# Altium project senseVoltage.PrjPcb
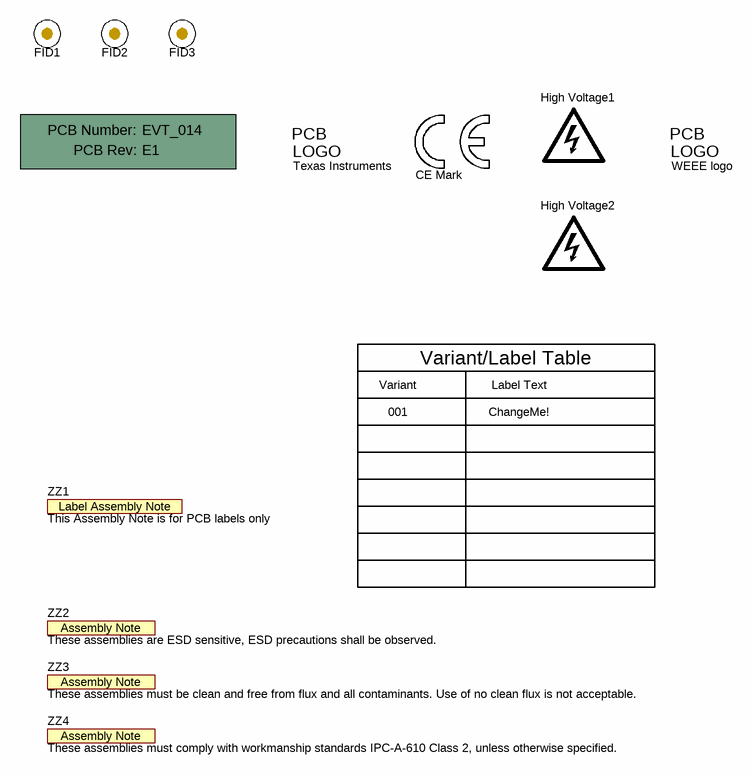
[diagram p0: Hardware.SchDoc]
CopyrightYear: 2018; PCB_Layout: Ramesh Ramamoorthy; PCB_Rev: E1; PRJ_Customer: EV Traction; PRJ_Engineer: Enter name of project lead; PRJ_Number: EVT_014; PRJ_Title: Isolated Sensing of Inverter and DC Bus Voltages; SCH_Rev: E1; TechSupport: http://www.ti.com/support; TID: N/A
2 sheets, 85 parts. Net scope: flat (ports and power ports of the same name join across sheets).
Board file: senseVoltage_r2.PcbDoc
Sheets:
  Hardware.SchDoc
  voltageSense_EVT.SchDoc

## Sheet Hardware.SchDoc
size 431 x 279 mm; Date: Not shown in title block; ApprovedBy: Not shown in title block; CheckedBy: Not shown in title block; Author: Not shown in title block; CompanyName: Not shown in title block; Engineer: Not shown in title block; Organization: Not shown in title block; Address1: Not shown in title block; Address2: Not shown in title block; Address3: Not shown in title block; Address4: Not shown in title block; DocumentNumber: 3; Revision: Use project parameter SCH_Rev; SheetNumber: 3; SheetTotal: 3; PageSetup: Record=PageOptions¦CenterHorizontal=True¦CenterVertical=True¦PrintScale=1.00¦XCorrection=1.00¦YCorrection=1.00¦PrintKind=0¦BorderSize=5000000¦LeftOffset=0¦BottomOffset=0¦Orientation=2¦PaperLength=1000¦PaperWidth=1000¦Scale=100¦PaperSource=15¦PrintQuality=600¦MediaType=1¦DitherType=10¦PaperKind=Letter¦PrintScaleMode=1

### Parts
!PCB1  Printed Circuit Board  (value not drawn)  (mechanical)
FID1  Fiducial  [Fiducial10-20]  (value not drawn)
FID2  Fiducial  [Fiducial10-20]  (value not drawn)
FID3  Fiducial  [Fiducial10-20]  (value not drawn)
High_Voltage1  DANGER HIGH VOLTAGE  [IEC_HighVoltage_Small]  (value not drawn)  (no BOM)
High_Voltage2  DANGER HIGH VOLTAGE  [IEC_HighVoltage_Small]  (value not drawn)  (no BOM)
Logo1  Texas Instruments  [TI_Stacked_Overlay_Small]  (no BOM)
Logo2  CE Mark  [CE_Mark_5mm]  (no BOM)
Logo3  WEEE logo  [WEEE_Minimum]  (no BOM)
ZZ1  This Assembly Note is for PCB labels only  [AssemblyNoteLabel]  (no BOM)
ZZ2  These assemblies are ESD sensitive, ESD precautions shall be observed.  [AssemblyNote]  (no BOM)
ZZ3  These assemblies must be clean and free from flux and all contaminants. Use of no clean flux is not acceptable.  [AssemblyNote]  (no BOM)
ZZ4  These assemblies must comply with workmanship standards IPC-A-610 Class 2, unless otherwise specified.  [AssemblyNote]  (no BOM)

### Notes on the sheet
- Variant
- Variant/Label Table
- Label Text
- 001
- ChangeMe!

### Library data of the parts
!PCB1 = CMP-0003618-2: Manufacturer: Any; PartNumber: EVT_014
FID1-FID3 = CMP-0077181-1: Fiducial mark.  There is nothing to buy or mount.
High_Voltage1 High_Voltage2 = CMP-0074835-1: IEC 61010-1 High Voltage Warning; SymbolCreator: a0412235
Logo1 = CMP-0074838-1: Texas Instrument Corporate Signature; SymbolCreator: a0412235; Lib Reference: TI_Logo; Library Reference: Logo
Logo2 = CMP-0074844-1: SymbolCreator: a0412235
Logo3 = CMP-0074769-1
ZZ1 = CMP-0003616-3
ZZ2 = CMP-0077236-1
ZZ3 = CMP-0077237-1
ZZ4 = CMP-0077238-1

## Sheet voltageSense_EVT.SchDoc
size A4; Date: Not shown in title block; ApprovedBy: Not shown in title block; CheckedBy: Not shown in title block; Author: Not shown in title block; CompanyName: Not shown in title block; Engineer: Not shown in title block; Organization: Not shown in title block; Address1: Not shown in title block; Address2: Not shown in title block; Address3: Not shown in title block; Address4: Not shown in title block; DocumentNumber: 2; Revision: Use project parameter SCH_Rev; SheetNumber: 2; SheetTotal: 3; PageSetup: Record=PageOptions¦CenterHorizontal=True¦CenterVertical=True¦PrintScale=1.00¦XCorrection=1.00¦YCorrection=1.00¦PrintKind=0¦BorderSize=5000000¦LeftOffset=0¦BottomOffset=0¦Orientation=2¦PaperLength=1000¦PaperWidth=1000¦Scale=100¦PaperSource=15¦PrintQuality=600¦MediaType=1¦DitherType=10¦PaperKind=Letter¦PrintScaleMode=1
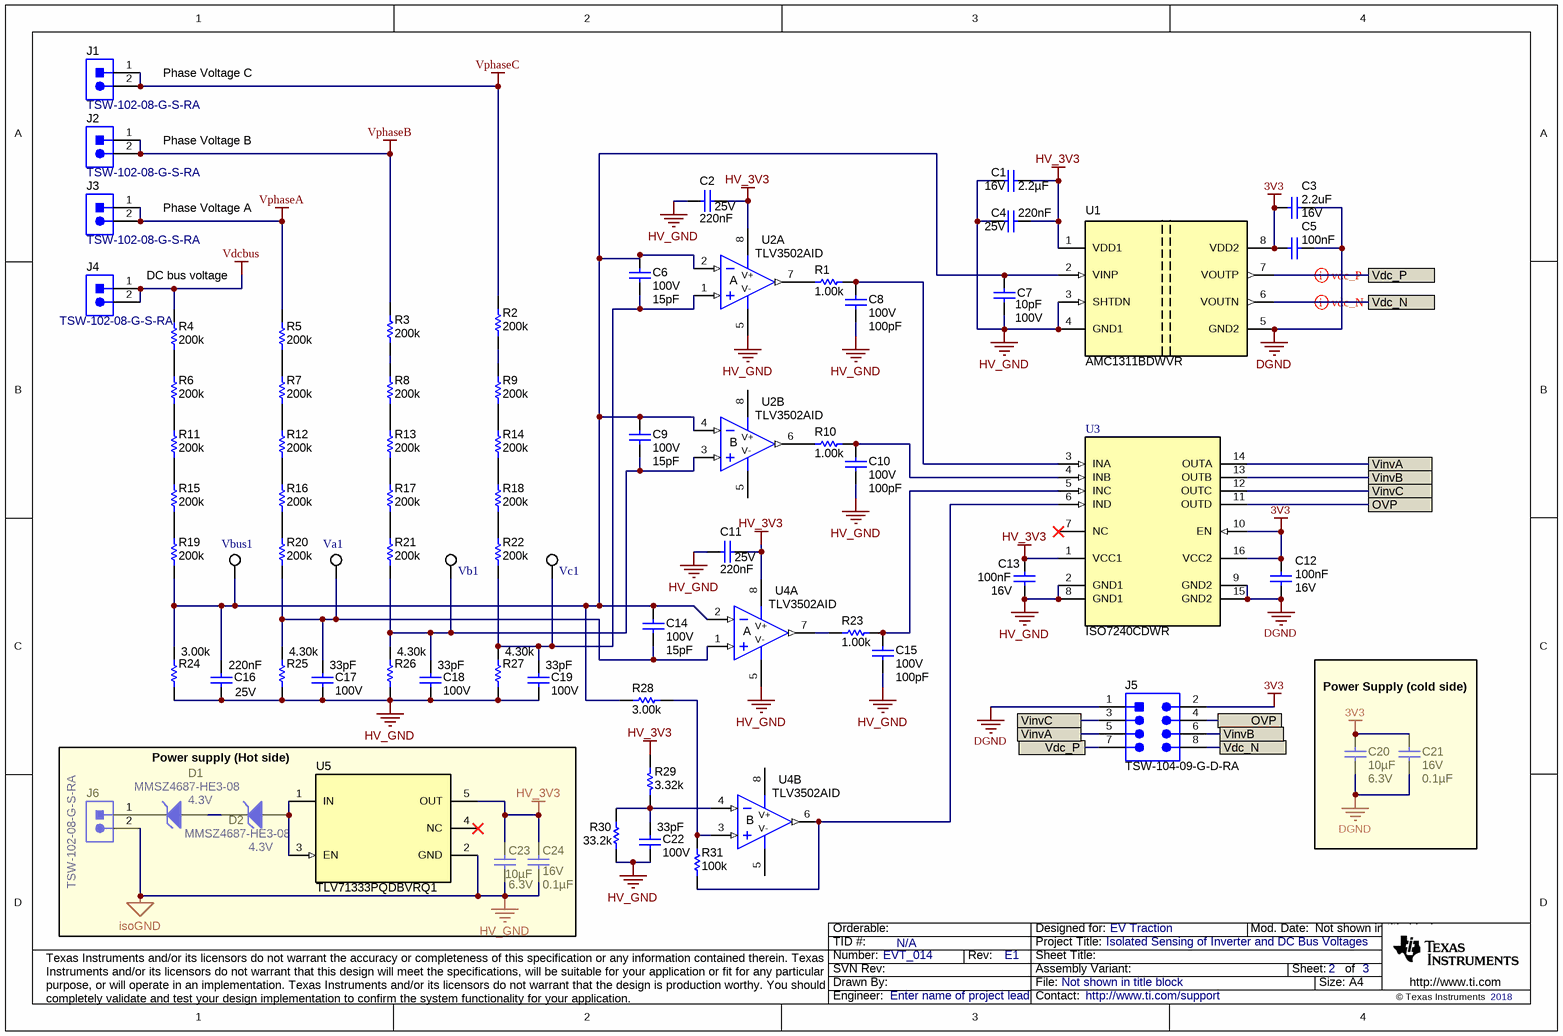
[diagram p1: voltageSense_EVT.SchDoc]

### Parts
C1  Cap_F: 2.2µF  VDC_V: 16V  [0805_HV]  (hidden comment: GRM219R71C225KE15)
C2  Cap_F: 220nF  VDC_V: 25V  [0805_HV]  (hidden comment: 08053C224JAT2A)
C3  VDC_V: 16V  ValueDisplayed: 2.2uF  [1206]  (hidden comment: GRM31MR71C225KA35L)
C4  Cap_F: 220nF  VDC_V: 25V  [0805_HV]  (hidden comment: 08053C224JAT2A)
C5  Cap_F: 100nF  [1206_190]  (hidden comment: C1206H104J3GACTU)
C6  VDC_V: 100V  ValueDisplayed: 15pF  [0805_HV]  (hidden comment: 08051A150JAT2A)
C7  VDC_V: 100V  ValueDisplayed: 10pF  [0805_HV]  (hidden comment: 08051A100CAT2A)
C8  VDC_V: 100V  ValueDisplayed: 100pF  [0805_HV]  (hidden comment: 08051A101JAT2A)
C9  VDC_V: 100V  ValueDisplayed: 15pF  [0805_HV]  (hidden comment: 08051A150JAT2A)
C10  VDC_V: 100V  ValueDisplayed: 100pF  [0805_HV]  (hidden comment: 08051A101JAT2A)
C11  Cap_F: 220nF  VDC_V: 25V  [0805_HV]  (hidden comment: 08053C224JAT2A)
C12  Cap_F: 100nF  VDC_V: 16V  [0805_HV]  (hidden comment: GRM219R71C104KA01D)
C13  Cap_F: 100nF  VDC_V: 16V  [0805_HV]  (hidden comment: GRM219R71C104KA01D)
C14  VDC_V: 100V  ValueDisplayed: 15pF  [0805_HV]  (hidden comment: 08051A150JAT2A)
C15  VDC_V: 100V  ValueDisplayed: 100pF  [0805_HV]  (hidden comment: 08051A101JAT2A)
C16  Cap_F: 220nF  VDC_V: 25V  [0805_HV]  (hidden comment: 08053C224JAT2A)
C17  VDC_V: 100V  ValueDisplayed: 33pF  [0805_HV]  (hidden comment: 08051A330JAT2A)
C18  VDC_V: 100V  ValueDisplayed: 33pF  [0805_HV]  (hidden comment: 08051A330JAT2A)
C19  VDC_V: 100V  ValueDisplayed: 33pF  [0805_HV]  (hidden comment: 08051A330JAT2A)
C20  Cap_F: 10µF  VDC_V: 6.3V  [0805_HV]  (hidden comment: GRM21BR70J106KE76L)
C21  VDC_V: 16V  ValueDisplayed: 0.1µF  [1206]  (hidden comment: 1206YC104KAT2A)
C22  VDC_V: 100V  ValueDisplayed: 33pF  [0805_HV]  (hidden comment: 08051A330JAT2A)
C23  Cap_F: 10µF  VDC_V: 6.3V  [0805_HV]  (hidden comment: GRM21BR70J106KE76L)
C24  VDC_V: 16V  ValueDisplayed: 0.1µF  [1206]  (hidden comment: 1206YC104KAT2A)
D1  MMSZ4687-HE3-08  value 4.3V  [SOD-123]
D2  MMSZ4687-HE3-08  value 4.3V  [SOD-123]
J1  TSW-102-08-G-S-RA  [TSW-102-08-G-S-RA]
J2  TSW-102-08-G-S-RA  [TSW-102-08-G-S-RA]
J3  TSW-102-08-G-S-RA  [TSW-102-08-G-S-RA]
J4  TSW-102-08-G-S-RA  [TSW-102-08-G-S-RA]
J5  TSW-104-09-G-D-RA  [Samtec_TSW-104-09-G-D-RA]
J6  TSW-102-08-G-S-RA  [TSW-102-08-G-S-RA]
R1  ValueDisplayed: 1.00k  [0805_HV]  (hidden comment: PHT0805Y1001BGT200)
R2  ValueDisplayed: 200k  [1206]  (hidden comment: ERJ-8ENF2003V)
R3  ValueDisplayed: 200k  [1206]  (hidden comment: ERJ-8ENF2003V)
R4  ValueDisplayed: 200k  [1206]  (hidden comment: ERJ-8ENF2003V)
R5  ValueDisplayed: 200k  [1206]  (hidden comment: ERJ-8ENF2003V)
R6  ValueDisplayed: 200k  [1206]  (hidden comment: ERJ-8ENF2003V)
R7  ValueDisplayed: 200k  [1206]  (hidden comment: ERJ-8ENF2003V)
R8  ValueDisplayed: 200k  [1206]  (hidden comment: ERJ-8ENF2003V)
R9  ValueDisplayed: 200k  [1206]  (hidden comment: ERJ-8ENF2003V)
R10  ValueDisplayed: 1.00k  [0805_HV]  (hidden comment: PHT0805Y1001BGT200)
R11  ValueDisplayed: 200k  [1206]  (hidden comment: ERJ-8ENF2003V)
R12  ValueDisplayed: 200k  [1206]  (hidden comment: ERJ-8ENF2003V)
R13  ValueDisplayed: 200k  [1206]  (hidden comment: ERJ-8ENF2003V)
R14  ValueDisplayed: 200k  [1206]  (hidden comment: ERJ-8ENF2003V)
R15  ValueDisplayed: 200k  [1206]  (hidden comment: ERJ-8ENF2003V)
R16  ValueDisplayed: 200k  [1206]  (hidden comment: ERJ-8ENF2003V)
R17  ValueDisplayed: 200k  [1206]  (hidden comment: ERJ-8ENF2003V)
R18  ValueDisplayed: 200k  [1206]  (hidden comment: ERJ-8ENF2003V)
R19  ValueDisplayed: 200k  [1206]  (hidden comment: ERJ-8ENF2003V)
R20  ValueDisplayed: 200k  [1206]  (hidden comment: ERJ-8ENF2003V)
R21  ValueDisplayed: 200k  [1206]  (hidden comment: ERJ-8ENF2003V)
R22  ValueDisplayed: 200k  [1206]  (hidden comment: ERJ-8ENF2003V)
R23  ValueDisplayed: 1.00k  [0805_HV]  (hidden comment: PHT0805Y1001BGT200)
R24  ValueDisplayed: 3.00k  [0805_HV]  (hidden comment: RG2012P-302-B-T5)
R25  ValueDisplayed: 4.30k  [0805_HV]  (hidden comment: RG2012P-432-B-T5)
R26  ValueDisplayed: 4.30k  [0805_HV]  (hidden comment: RG2012P-432-B-T5)
R27  ValueDisplayed: 4.30k  [0805_HV]  (hidden comment: RG2012P-432-B-T5)
R28  ValueDisplayed: 3.00k  [0805_HV]  (hidden comment: RG2012P-302-B-T5)
R29  ValueDisplayed: 3.32k  [0805_HV]  (hidden comment: RR1220P-3321-D-M)
R30  ValueDisplayed: 33.2k  [0805_HV]  (hidden comment: RG2012P-3322-B-T5)
R31  ValueDisplayed: 100k  [0805_HV]  (hidden comment: RR1220P-104-D)
U1  AMC1311BDWVR  [DWV0008A]
U2  TLV3502AID  [D0008A_N]  (parts A,B of 2)
U3  ISO7240CDWR  [DW0016B_HV]
U4  TLV3502AID  [D0008A_N]  (parts A,B of 2)
U5  TLV71333PQDBVRQ1  [DBV0005A_N]
Va1  5002  [Keystone5002]  (value not drawn)
Vb1  5002  [Keystone5002]  (value not drawn)
Vbus1  5002  [Keystone5002]  (value not drawn)
Vc1  5002  [Keystone5002]  (value not drawn)

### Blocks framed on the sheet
Power Supply (cold side): C20 C21
Power supply (Hot side): C23 C24 D1 D2 J6 U5

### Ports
OVP, Vdc_N, Vdc_P, VinvA, VinvB, VinvC

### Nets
3V3: C3.2 C5.2 C12.1 C20.2 C21.1 J5.2 U1.8(VDD2) U3.10(EN) U3.16(VCC2)
DGND: C3.1 C5.1 C12.2 C20.1 C21.2 J5.1 U1.5(GND2) U3.9(GND2) U3.15(GND2)
HV_3V3: C1.1 C2.2 C4.1 C11.2 C13.1 C23.2 C24.1 R29.2 U1.1(VDD1) U2.8(V+) U3.1(VCC1) U4.8(V+) U5.5(OUT)
HV_GND: C1.2 C2.1 C4.2 C7.2 C8.2 C10.2 C11.1 C13.2 C15.2 C16.1 C17.2 C18.2 C19.2 C22.2 C23.1 C24.2 J6.2 R24.1 R25.1 R26.1 R27.1 R30.1 U1.3(SHTDN) U1.4(GND1) U2.5(V-) U3.2(GND1) U3.8(GND1) U4.5(V-) U5.2(GND)  [also labelled isoGND]
Vdcbus: J4.1 J4.2 R4.2
VphaseA: J3.1 J3.2 R5.2
VphaseB: J2.1 J2.2 R3.2
VphaseC: J1.1 J1.2 R2.2
OVP: J5.4 U3.11(OUTD) ; port OVP
Vdc_N: J5.8 U1.6(VOUTN) ; port Vdc_N
Vdc_P: J5.7 U1.7(VOUTP) ; port Vdc_P
VinvA: J5.5 U3.14(OUTA) ; port VinvA
VinvB: J5.6 U3.13(OUTB) ; port VinvB
VinvC: J5.3 U3.12(OUTC) ; port VinvC
NetC6_1: C6.1 C19.1 R22.1 R27.2 U2.1(+IN_A) Vc1.1
NetC6_2: C6.2 C7.1 C9.2 C14.2 C16.2 R19.1 R24.2 R28.2 U1.2(VINP) U2.2(-IN_A) U2.4(-IN_B) U4.2(-IN_A) Vbus1.1
NetC8_1: C8.1 R1.2 U3.3(INA)
NetC9_1: C9.1 C18.1 R21.1 R26.2 U2.3(+IN_B) Vb1.1
NetC10_1: C10.1 R10.2 U3.4(INB)
NetC14_1: C14.1 C17.1 R20.1 R25.2 U4.1(+IN_A) Va1.1
NetC15_1: C15.1 R23.2 U3.5(INC)
NetC22_1: C22.1 R29.1 R30.2 U4.4(-IN_B)
NetD1_1: D1.1(K) J6.1
NetD1_2: D1.2(A) D2.1(K)
NetD2_2: D2.2(A) U5.1(IN) U5.3(EN)
NetR1_1: R1.1 U2.7(OUT_A)
NetR2_1: R2.1 R9.2
NetR3_1: R3.1 R8.2
NetR4_1: R4.1 R6.2
NetR5_1: R5.1 R7.2
NetR6_1: R6.1 R11.2
NetR7_1: R7.1 R12.2
NetR8_1: R8.1 R13.2
NetR9_1: R9.1 R14.2
NetR10_1: R10.1 U2.6(OUT_B)
NetR11_1: R11.1 R15.2
NetR12_1: R12.1 R16.2
NetR13_1: R13.1 R17.2
NetR14_1: R14.1 R18.2
NetR15_1: R15.1 R19.2
NetR16_1: R16.1 R20.2
NetR17_1: R17.1 R21.2
NetR18_1: R18.1 R22.2
NetR23_1: R23.1 U4.7(OUT_A)
NetR28_1: R28.1 R31.2 U4.3(+IN_B)
NetR31_1: R31.1 U3.6(IND) U4.6(OUT_B)

Not connected (* = marked no-connect by the designer): U3 7(NC)*; U5 4(NC)*

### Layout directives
differential pair: Vdc_N, Vdc_P

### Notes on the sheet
- (near J1) Phase Voltage C
- Phase Voltage B
- Phase Voltage A
- DC bus voltage

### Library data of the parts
C1 = CMP-0008211-2: CAP, CERM, 2.2 uF, 16 V, +/- 10%, X7R, 0805; Manufacturer: MuRata; TaMin_C: -55°C; Polarized: N; SizeAreaWB_mm2: 6.75; Value1: Unknown; U/M: EA; Value: 2.2uF; TaMax_C: 125°C; SizeZ_mm: 1.45; SizeX_mm: 2; SizeY_mm: 1.25; Cap_Case: 0805; SizeArea_mm2: 2.5; AEC Category: Q200
C2 C4 C11 C16 = CMP-0007570-1: CAP, CERM, 0.22 uF, 25 V, +/- 5%, X7R, 0805; Manufacturer: AVX; TaMin_C: -55°C; ESR_ohm: 0.016; Polarized: N; SizeAreaWB_mm2: 6.75; Value1: 0.016 ohm; U/M: EA; Value: 0.22uF; TaMax_C: 125°C; SizeZ_mm: 1.45; SizeX_mm: 2; SizeY_mm: 1.25; Cap_Case: 0805; SizeArea_mm2: 2.5; AEC Category: Q200
C3 = CMP-0008987-1: CAP, CERM, 2.2 uF, 16 V, +/- 10%, X7R, 1206; Manufacturer: MuRata; TaMin_C: -55°C; ESR_ohm: 6m; Polarized: N; SizeAreaWB_mm2: 10.92; Value1: 0.006 ohm; U/M: EA; Value: 2.2uF; TaMax_C: 125°C; SizeZ_mm: 1.35; SizeX_mm: 3.2; SizeY_mm: 1.6; SizeArea_mm2: 5.12; Cap_F: 2.2µF; AEC Category: Q200
C5 = CMP-0008641-1: CAP, CERM, 0.1 uF, 25 V, +/- 5%, C0G/NP0, 1206_190; Manufacturer: Kemet; TaMin_C: -55°C; Polarized: N; SizeAreaWB_mm2: 10.92; Value1: Unknown; U/M: EA; Value: 0.1uF; TaMax_C: 200°C; SizeZ_mm: 1.9; SizeX_mm: 3.2; SizeY_mm: 1.6; Cap_Case: 1206; Value2: 25V; SizeArea_mm2: 5.12; AEC Category: Q200
C6 C9 C14 = CMP-0007520-1: CAP, CERM, 15 pF, 100 V, +/- 5%, C0G/NP0, 0805; Manufacturer: AVX; TaMin_C: -55°C; ESR_ohm: 1.185; Polarized: N; SizeAreaWB_mm2: 6.75; Value1: 1.185 ohm; U/M: EA; Value: 15pF; TaMax_C: 125°C; SizeZ_mm: 1.45; SizeX_mm: 2; SizeY_mm: 1.25; Cap_Case: 0805; SizeArea_mm2: 2.5; AEC Category: Q200
C7 = CMP-0007513-1: CAP, CERM, 10 pF, 100 V, +/- 5%, C0G/NP0, 0805; Manufacturer: AVX; TaMin_C: -55°C; ESR_ohm: 1.561; Polarized: N; SizeAreaWB_mm2: 6.75; Value1: 1.561 ohm; U/M: EA; Value: 10pF; TaMax_C: 125°C; SizeZ_mm: 1.45; SizeX_mm: 2; SizeY_mm: 1.25; Cap_Case: 0805; SizeArea_mm2: 2.5; AEC Category: Q200
C8 C10 C15 = CMP-0007517-1: CAP, CERM, 100 pF, 100 V, +/- 5%, C0G/NP0, 0805; Manufacturer: AVX; TaMin_C: -55°C; ESR_ohm: 0.356; Polarized: N; SizeAreaWB_mm2: 6.75; Value1: 0.356 ohm; U/M: EA; Value: 100pF; TaMax_C: 125°C; SizeZ_mm: 1.45; SizeX_mm: 2; SizeY_mm: 1.25; Cap_Case: 0805; SizeArea_mm2: 2.5; AEC Category: Q200
C12 C13 = CMP-0008209-1: CAP, CERM, 0.1 uF, 16 V, +/- 10%, X7R, 0805; Manufacturer: MuRata; TaMin_C: -55°C; Polarized: N; SizeAreaWB_mm2: 6.75; Value1: Unknown; U/M: EA; Value: 0.1uF; TaMax_C: 125°C; SizeZ_mm: 1.45; SizeX_mm: 2; SizeY_mm: 1.25; Cap_Case: 0805; SizeArea_mm2: 2.5; AEC Category: Q200
C17-C19 C22 = CMP-0007529-1: CAP, CERM, 33 pF, 100 V, +/- 5%, C0G/NP0, 0805; Manufacturer: AVX; TaMin_C: -55°C; ESR_ohm: 0.708; Polarized: N; SizeAreaWB_mm2: 6.75; Value1: 0.708 ohm; U/M: EA; Value: 33pF; TaMax_C: 125°C; SizeZ_mm: 1.45; SizeX_mm: 2; SizeY_mm: 1.25; Cap_Case: 0805; SizeArea_mm2: 2.5; AEC Category: Q200
C20 C23 = CMP-0008311-2: CAP, CERM, 10 uF, 6.3 V, +/- 10%, X7R, 0805; Manufacturer: MuRata; TaMin_C: -55°C; Polarized: N; SizeAreaWB_mm2: 6.75; Value1: Unknown; U/M: EA; Value: 10uF; TaMax_C: 125°C; SizeZ_mm: 1.45; SizeX_mm: 2; SizeY_mm: 1.25; Cap_Case: 0805; SizeArea_mm2: 2.5; AEC Category: Q200
C21 C24 = CMP-0860522-1: CAP, CERM, 0.1 µF, 16 V,+/- 10%, X7R, 1206; Manufacturer: AVX; SizeArea_mm2: 5.12; SizeX_mm: 3.2; Value: 0.1uF; SizeAreaWB_mm2: 10.92; Cap_F: 100nF; SizeZ_mm: 1.35; AEC Category: Q200; Polarized: N; U/M: EA; SizeY_mm: 1.6; TaMin_C: -55°C; TaMax_C: 125°C
D1 D2 = CMP-0077560-1: Diode, Zener, 4.3 V, 500 mW, AEC-Q101, SOD-123; Manufacturer: Vishay-Semiconductor; SizeAreaWB_mm2: 13.095; SizeArea_mm2: 6.545; AEC Qualified: Y; AEC Category: Q101; SizeZ_mm: 1.35; RJA_CperW: 340; Power_W: 500mW; SizeY_mm: 1.7; U/M: EA; Value1: 0.5W; SizeX_mm: 3.85
J1-J4 J6 = CMP-0055976-1: Header, 100mil, 2x1, Gold, R/A, TH; Manufacturer: Samtec; Cert_VDE: N; CNHeader: FALSE; Current_A: 6.3A; Green_Lifecycle: Active; Gender: Male; Cert_CSA: Y; Green_REACh: Passed; Voltage_V: 550V; Row_Count: 1; Pitch_mm: 2.54
J5 = CMP-0075584-1: Header, 100mil, 4x2, Gold, R/A, TH; Manufacturer: Samtec; Pitch_mm: 2.54; Cert_VDE: N; Gender: Male; Cert_CSA: Y; Current_A: 6.3A; Voltage_V: 550V; CT: False; Row_Count: 2; CNHeader: True
R1 R10 R23 = CMP-0018844-1: RES, 1.00 k, 0.1%, 0.06 W, 0805; Manufacturer: Vishay Sfernice; Power_W: 60mW; TempCo: 15 ppm/C; Value_Code: 1k00; U/M: EA; Value: 1.00k; EIA_Code: E192; Res_ohm: 1k; SizeX_mm: 2; SizeY_mm: 1.25; SizeZ_mm: 1.45; Value2: 0.06W; SizeArea_mm2: 2.5; VDC_V: 150V; AEC Category: Q200
R2-R9 R11-R22 = CMP-0017437-3: RES, 200 k, 1%, 0.25 W, AEC-Q200 Grade 0, 1206; Manufacturer: Panasonic; Power_W: 250mW; TempCo: 100 ppm/C; Value: 200k; EIA_Code: E96; SizeX_mm: 3.2; SizeY_mm: 1.6; SizeZ_mm: 1.35; Value2: 0.25W; SizeArea_mm2: 5.12; AEC Qualified: Y; VDC_V: 200V; AEC Category: Q200; AEC Grade: 0; SizeAreaWB_mm2: 10.92
R24 R28 = CMP-0018951-1: RES, 3.00 k, 0.1%, 0.125 W, 0805; Manufacturer: Susumu Co Ltd; Power_W: 125mW; TempCo: 25 ppm/C; Value_Code: 3k00; U/M: EA; Value: 3.00k; Res_ohm: 3k; SizeX_mm: 2; SizeY_mm: 1.25; SizeZ_mm: 1.45; Value2: 0.125W; SizeArea_mm2: 2.5; VDC_V: 100V; AEC Category: Q200
R25-R27 = CMP-0018983-1: RES, 4.30 k, 0.1%, 0.125 W, 0805; Manufacturer: Susumu Co Ltd; Power_W: 125mW; TempCo: 25 ppm/C; Value_Code: 4k30; U/M: EA; Value: 4.30k; Res_ohm: 4.3k; SizeX_mm: 2; SizeY_mm: 1.25; SizeZ_mm: 1.45; Value2: 0.125W; SizeArea_mm2: 2.5; VDC_V: 100V; AEC Category: Q200
R29 = CMP-0019250-1: RES, 3.32 k, 0.5%, 0.1 W, 0805; Manufacturer: Susumu Co Ltd; Power_W: 100mW; TempCo: 25 ppm/C; Value_Code: 3k32; U/M: EA; Value: 3.32k; EIA_Code: E192; SizeX_mm: 2; SizeY_mm: 1.25; SizeZ_mm: 1.45; Value2: 0.1W; SizeArea_mm2: 2.5; VDC_V: 100V; AEC Category: Q200
R30 = CMP-0018959-1: RES, 33.2 k, 0.1%, 0.125 W, 0805; Manufacturer: Susumu Co Ltd; Power_W: 125mW; TempCo: 25 ppm/C; Value_Code: 33k2; U/M: EA; Value: 33.2k; EIA_Code: E192; SizeX_mm: 2; SizeY_mm: 1.25; SizeZ_mm: 1.45; Value2: 0.125W; SizeArea_mm2: 2.5; VDC_V: 100V; AEC Category: Q200
R31 = CMP-0019096-1: RES, 100 k, 0.5%, 0.1 W, 0805; Manufacturer: Susumu Co Ltd; Power_W: 100mW; TempCo: 25 ppm/C; U/M: EA; Value: 100k; EIA_Code: E192; SizeX_mm: 2; SizeY_mm: 1.25; SizeZ_mm: 1.45; Value2: 0.1W; SizeArea_mm2: 2.5; VDC_V: 100V; AEC Category: Q200
U1 = CMP-0078341-1: Precision, 2-V Input, Reinforced Isolated Amplifier, DWV0008A (SOIC-8); Alternate Manufacturer: Texas Instruments; SizeAreaWB_mm2: 105.975; SizeZ_mm: 2.8; SizeX_mm: 11.5; SizeY_mm: 5.85; SizeArea_mm2: 67.275; CompType: IC; AEC Qualified: N; AEC Category: Q200
U2 U4 = CMP-0065423-1: 4.5ns Rail-to-Rail Comparator, D0008A (SOIC-8); Alternate Manufacturer: Texas Instruments; SizeAreaWB_mm2: 56.58; U/M: EA; SizeZ_mm: 1.75; SizeX_mm: 4.9; SizeY_mm: 6.2; SizeArea_mm2: 30.38; CompType: IC
U3 = CMP-0029379-2: 2.5 kVrms, 25 Mbps, 4-Channel 4/0 Digital Isolator, DW0016B (SOIC-16); Manufacturer: Texas Instruments; SizeX_mm: 10.4; SizeY_mm: 10.3; SizeZ_mm: 2.65; Supply Voltage(s)(V): 3.3, 5; Rating: Catalog; SizeAreaWB_mm2: 152.52; Insulation Rating(VRMS): 2500; AEC Category: Q200; CompType: IC; Datarate(Mbps): 25; Prop Delay(Max)(ns): 30; SizeArea_mm2: 107.12; TTL/CMOS Input Threshold: TTL; AEC Qualified: N; Thermal Shutdown: No; Input Noise Filter: Yes
U5 = CMP-0073750-1: Capacitor-Free, 150-mA, LDO Regulator w/ Foldback Current Limit, DBV0005A (SOT-23-5); Alternate Manufacturer: Texas Instruments; SizeAreaWB_mm2: 14.82; U/M: EA; SizeZ_mm: 1.45; SizeX_mm: 2.8; SizeY_mm: 2.9; SizeArea_mm2: 8.12; CompType: IC
Va1 Vb1 Vbus1 Vc1 = CMP-0055139-1: Test Point, Miniature, White, TH; Manufacturer: Keystone; ContactFinish: Silver; Green_Lifecycle: Active; Green_REACh: Passed; CNHeader: FALSE; CT: TRUE

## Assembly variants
001: not fitted FID1 FID2 FID3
